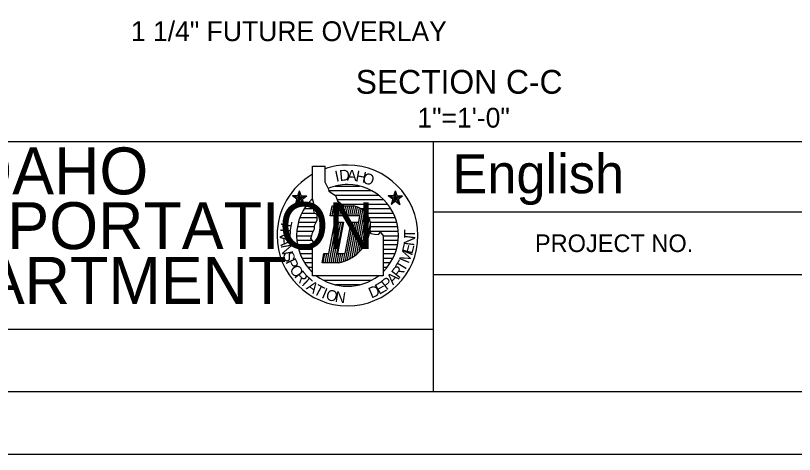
# Model space of a CAD drawing. Extents: x 0 to 34, y 0 to 23.5.
# Drawn here: x 15.91 to 22.13, y 0 to 3.51 of the extents above; entities that cross this region are included whole.
import ezdxf

# ---------------------------------------------------------------- set-up
doc = ezdxf.new("R2010")
doc.units = 0
for name, color, linetype in [('BORDER_ANNO_Cutsheet', 7, 'Continuous'), ('BRDG_ANNO_Anno-Sheet', 7, 'Continuous'), ('BRDG_ANNO_General-Notes', 7, 'Continuous')]:
    doc.layers.add(name, color=color, linetype=linetype)

msp = doc.modelspace()

# ---------------------------------------------------------------- linework, layer by layer
at = {"layer": 'BORDER_ANNO_Cutsheet'}
msp.add_lwpolyline([(0, 22), (34, 22), (34, 0), (0, 0)], close=True, dxfattribs=at)
at = {"layer": 'BRDG_ANNO_Anno-Sheet'}
for p, q in [((1.5, 2.5), (19.25, 2.5)), ((19.25, 0.5), (19.25, 2.5)), ((19.25, 2.5), (33.5, 2.5)), ((18.2844, 2.0425), (18.2844, 2.3031)), ((18.2844, 2.3031), (18.3831, 2.3031)), ((18.3831, 2.1731), (18.3831, 2.3031)), ((18.3831, 2.1731), (18.4094, 2.1262)), ((18.4094, 2.1262), (18.4144, 2.105)), ((18.465, 2.1444), (18.6581, 2.1444)), ((18.2012, 2.04), (18.1225, 2.0656)), ((18.1656, 2.0656), (18.1225, 2.0656)), ((18.1575, 2.04), (18.1225, 2.0656)), ((18.1931, 2.0656), (18.1438, 1.9981)), ((18.1575, 2.04), (18.2369, 2.0656)), ((18.1656, 2.0656), (18.1794, 2.1069)), ((18.1656, 2.0656), (18.215, 1.9981)), ((18.1794, 2.0237), (18.1794, 2.1069)), ((18.1931, 2.0656), (18.1794, 2.1069)), ((18.1931, 2.0656), (18.2369, 2.0656)), ((18.2012, 2.04), (18.2369, 2.0656)), ((18.4144, 2.105), (18.4662, 2.0688)), ((18.4169, 2.1081), (18.7506, 2.1081)), ((18.465, 2.0725), (18.8069, 2.0725)), ((18.4662, 2.0688), (18.4825, 2.0269)), ((18.9675, 2.04), (18.8881, 2.0656)), ((18.9237, 2.04), (18.8881, 2.0656)), ((18.9319, 2.0656), (18.8881, 2.0656)), ((18.9594, 2.0656), (18.91, 1.9981)), ((18.9237, 2.04), (19.0025, 2.0656)), ((18.9319, 2.0656), (18.9456, 2.1069)), ((18.9319, 2.0656), (18.9812, 1.9981)), ((18.9456, 2.0237), (18.9456, 2.1069)), ((18.9594, 2.0656), (18.9456, 2.1069)), ((18.9594, 2.0656), (19.0025, 2.0656)), ((18.9675, 2.04), (19.0025, 2.0656)), ((18.1575, 2.04), (18.1438, 1.9981)), ((18.1794, 2.0237), (18.1438, 1.9981)), ((18.1794, 2.0237), (18.215, 1.9981)), ((18.2012, 2.04), (18.215, 1.9981)), ((18.2419, 2.0006), (18.2937, 2.0006)), ((18.2744, 2.0362), (18.2862, 2.0362)), ((18.2944, 2.0063), (18.2844, 2.0425)), ((18.2944, 1.975), (18.2944, 2.0063)), ((18.4787, 2.0362), (18.8506, 2.0362)), ((18.4825, 2.0269), (18.5344, 1.9856)), ((18.5156, 2.0006), (18.8825, 2.0006)), ((18.9237, 2.04), (18.91, 1.9981)), ((18.9456, 2.0237), (18.91, 1.9981)), ((18.9456, 2.0237), (18.9812, 1.9981)), ((18.9675, 2.04), (18.9812, 1.9981)), ((18.1969, 1.9281), (18.2981, 1.9281)), ((18.2169, 1.9644), (18.2925, 1.9644)), ((18.2944, 1.9487), (18.2944, 1.975)), ((18.3, 1.9281), (18.2944, 1.9487)), ((18.3206, 1.9175), (18.3, 1.9281)), ((18.425, 1.9069), (18.4406, 1.9856)), ((18.4394, 1.9069), (18.4537, 1.9856)), ((18.4406, 1.9856), (18.6125, 1.9856)), ((18.455, 1.9069), (18.47, 1.9856)), ((18.4712, 1.9069), (18.4856, 1.9856)), ((18.4869, 1.9069), (18.5019, 1.9856)), ((18.5025, 1.9069), (18.5175, 1.9856)), ((18.5188, 1.9069), (18.5331, 1.9856)), ((18.5344, 1.9069), (18.5494, 1.9856)), ((18.5506, 1.9069), (18.565, 1.9856)), ((18.5663, 1.9069), (18.5813, 1.9856)), ((18.5825, 1.9069), (18.5969, 1.9856)), ((18.5981, 1.9069), (18.6131, 1.9856)), ((18.5994, 1.5744), (18.6719, 1.9619)), ((18.6137, 1.9069), (18.6281, 1.9812)), ((18.6175, 1.5856), (18.6863, 1.9519)), ((18.63, 1.9069), (18.6431, 1.9769)), ((18.6363, 1.6006), (18.6994, 1.9387)), ((18.6456, 1.9069), (18.6575, 1.97)), ((18.6687, 1.9644), (18.9075, 1.9644)), ((18.71, 1.9281), (18.9275, 1.9281)), ((19.25, 1.9375), (22.25, 1.9375)), ((18.1812, 1.8925), (18.3187, 1.8925)), ((18.31, 1.85), (18.3206, 1.8756)), ((18.3206, 1.8912), (18.3206, 1.9175)), ((18.3206, 1.8756), (18.3206, 1.8912)), ((18.6612, 1.9069), (18.425, 1.9069)), ((18.6519, 1.855), (18.6612, 1.9069)), ((18.6556, 1.6187), (18.7125, 1.9244)), ((18.6756, 1.64), (18.725, 1.9062)), ((18.6969, 1.6687), (18.7369, 1.8819)), ((18.7325, 1.8925), (18.9431, 1.8925)), ((18.1625, 1.8206), (18.2981, 1.8206)), ((18.1706, 1.8562), (18.3113, 1.8562)), ((18.3, 1.8287), (18.31, 1.85)), ((18.3, 1.8031), (18.3, 1.8287)), ((18.4144, 1.605), (18.4612, 1.855)), ((18.4162, 1.5319), (18.4769, 1.855)), ((18.4325, 1.5319), (18.4931, 1.855)), ((18.4481, 1.5319), (18.5087, 1.855)), ((18.4612, 1.855), (18.53, 1.855)), ((18.4644, 1.5319), (18.525, 1.855)), ((18.53, 1.855), (18.4831, 1.605)), ((18.5437, 1.605), (18.5906, 1.855)), ((18.5469, 1.5475), (18.6044, 1.855)), ((18.5637, 1.555), (18.62, 1.855)), ((18.5813, 1.5631), (18.6363, 1.855)), ((18.5906, 1.855), (18.6519, 1.855)), ((18.7219, 1.7175), (18.7456, 1.845)), ((18.7444, 1.8562), (18.9544, 1.8562)), ((18.7475, 1.8206), (18.9625, 1.8206)), ((18.1562, 1.7481), (18.2775, 1.7481)), ((18.1575, 1.7844), (18.2906, 1.7844)), ((18.2688, 1.725), (18.2787, 1.7506)), ((18.2787, 1.7506), (18.2844, 1.7719)), ((18.2844, 1.7719), (18.3, 1.8031)), ((18.7406, 1.7775), (18.7481, 1.7662)), ((18.7425, 1.7844), (18.9675, 1.7844)), ((18.7481, 1.7662), (18.7794, 1.7612)), ((18.7794, 1.7612), (18.8106, 1.7562)), ((18.8106, 1.7562), (18.8262, 1.7769)), ((18.8262, 1.7769), (18.8469, 1.7456)), ((18.845, 1.7481), (18.9688, 1.7481)), ((18.8469, 1.7456), (18.8469, 1.4275)), ((18.1581, 1.7125), (18.2812, 1.7125)), ((18.2844, 1.7094), (18.2688, 1.725)), ((18.2944, 1.6937), (18.2844, 1.7094)), ((18.3, 1.6831), (18.2944, 1.6937)), ((18.3, 1.6675), (18.3, 1.6831)), ((18.8475, 1.7125), (18.9669, 1.7125)), ((18.1631, 1.6763), (18.2981, 1.6763)), ((18.1713, 1.6406), (18.2837, 1.6406)), ((18.2844, 1.6519), (18.3, 1.6675)), ((18.2844, 1.4275), (18.2844, 1.6519)), ((18.8469, 1.6763), (18.9619, 1.6763)), ((18.8469, 1.6406), (18.9537, 1.6406)), ((18.1837, 1.6044), (18.2825, 1.6044)), ((18.1994, 1.5681), (18.2825, 1.5681)), ((18.3594, 1.5319), (18.3731, 1.605)), ((18.3687, 1.5319), (18.3825, 1.605)), ((18.3731, 1.605), (18.4144, 1.605)), ((18.385, 1.5319), (18.3987, 1.605)), ((18.4006, 1.5319), (18.4144, 1.605)), ((18.48, 1.5319), (18.4937, 1.605)), ((18.4831, 1.605), (18.5437, 1.605)), ((18.4962, 1.5325), (18.51, 1.605)), ((18.5131, 1.5369), (18.5256, 1.605)), ((18.53, 1.5419), (18.5412, 1.605)), ((18.8469, 1.6044), (18.9413, 1.6044)), ((18.8469, 1.5681), (18.925, 1.5681)), ((18.22, 1.5325), (18.2831, 1.5325)), ((18.2456, 1.4962), (18.2825, 1.4962)), ((18.4925, 1.5319), (18.3594, 1.5319)), ((18.8469, 1.5325), (18.905, 1.5325)), ((18.8469, 1.4962), (18.88, 1.4962)), ((18.2775, 1.4606), (18.2837, 1.4606)), ((19.25, 1.4375), (22.25, 1.4375)), ((18.8469, 1.4275), (18.2844, 1.4275)), ((18.7506, 1.3912), (18.3719, 1.3912)), ((18.6587, 1.3556), (18.4675, 1.3556)), ((14, 1), (19.25, 1))]:
    msp.add_line(p, q, dxfattribs=at)
msp.add_lwpolyline([(1.5, 21.5), (33.5, 21.5), (33.5, 0.5), (1.5, 0.5)], close=True, dxfattribs=at)
for centre, radius, start, end in [((18.5625, 1.75), 0.5625, 90, 108.596), ((18.5625, 1.75), 0.5625, 0, 90), ((18.5625, 1.75), 0.5625, 119.63312, 180), ((18.5625, 1.75), 0.4063, 90, 112.14518), ((18.5625, 1.75), 0.4063, 0, 90), ((18.5625, 1.75), 0.4063, 133.19257, 180), ((18.5833, 1.8241), 0.1641, 343.49805, 79.73615), ((18.5625, 1.75), 0.5625, 180, 270), ((18.5625, 1.75), 0.4063, 180.26444, 226.79463), ((18.4349, 1.8382), 0.3117, 280.64795, 348.77185), ((18.5625, 1.75), 0.5625, 270, 0), ((18.5625, 1.75), 0.4063, 314.427, 0), ((18.5625, 1.75), 0.4063, 232.5658, 270), ((18.5625, 1.75), 0.4063, 270, 307.45359)]:
    msp.add_arc(centre, radius, start, end, dxfattribs=at)

# ---------------------------------------------------------------- texts
for s, height, p in [('IDAHO', 0.375, (15.3837, 2.0781)), ('English', 0.3125, (19.4006, 2.0869)), ('TRANSPORTATION', 0.375, (14.1469, 1.6406)), ('PROJECT NO.', 0.140625, (20.0591, 1.6175)), ('DEPARTMENT', 0.375, (14.6194, 1.2031))]:
    msp.add_text(s, height=height, dxfattribs=at).set_placement(p)
for s, rotation, p in [('I', 11.95188, (18.4719, 2.1781)), ('D', 5.21184, (18.5012, 2.1844)), ('A', 357.8718, (18.5569, 2.1881)), ('H', 349.63177, (18.6219, 2.1837)), ('O', 342.19173, (18.6744, 2.1731)), ('T', 259.42648, (18.0381, 1.8756)), ('R', 266.0275, (18.0263, 1.8075)), ('N', 83.19321, (19.095, 1.6631)), ('T', 90.49256, (19.1019, 1.7294)), ('A', 273.76404, (18.0231, 1.7406)), ('E', 75.61046, (19.0794, 1.5969)), ('N', 280.37584, (18.0287, 1.6712)), ('S', 287.92792, (18.0431, 1.6038)), ('M', 67.71394, (19.0506, 1.5206)), ('P', 295.49755, (18.0656, 1.5406)), ('T', 59.03624, (19.0137, 1.455)), ('O', 302.64464, (18.0956, 1.48)), ('R', 52.33438, (18.9737, 1.4012)), ('R', 309.90789, (18.1337, 1.4225)), ('T', 317.1211, (18.1775, 1.3712)), ('A', 45, (18.9256, 1.3506)), ('A', 324.63754, (18.2281, 1.3256)), ('E', 30.54757, (18.8156, 1.2737)), ('P', 37.66562, (18.8731, 1.3094)), ('T', 331.75026, (18.2844, 1.2869)), ('I', 337.0213, (18.3494, 1.2537)), ('O', 343.32869, (18.3825, 1.2406)), ('D', 22.98872, (18.7531, 1.2456)), ('N', 351.65981, (18.4587, 1.22))]:
    msp.add_text(s, height=0.0869, rotation=rotation, dxfattribs=at).set_placement(p)
at = {"layer": 'BRDG_ANNO_General-Notes'}
for s, height, p in [('1 1/4" FUTURE OVERLAY', 0.158333, (16.833, 3.3029)), ('SECTION C-C', 0.19, (18.6281, 2.8823)), ('1"=1\'-0"', 0.15833, (19.1205, 2.6115))]:
    msp.add_text(s, height=height, dxfattribs=at).set_placement(p)

doc.saveas('drawing.dxf')
